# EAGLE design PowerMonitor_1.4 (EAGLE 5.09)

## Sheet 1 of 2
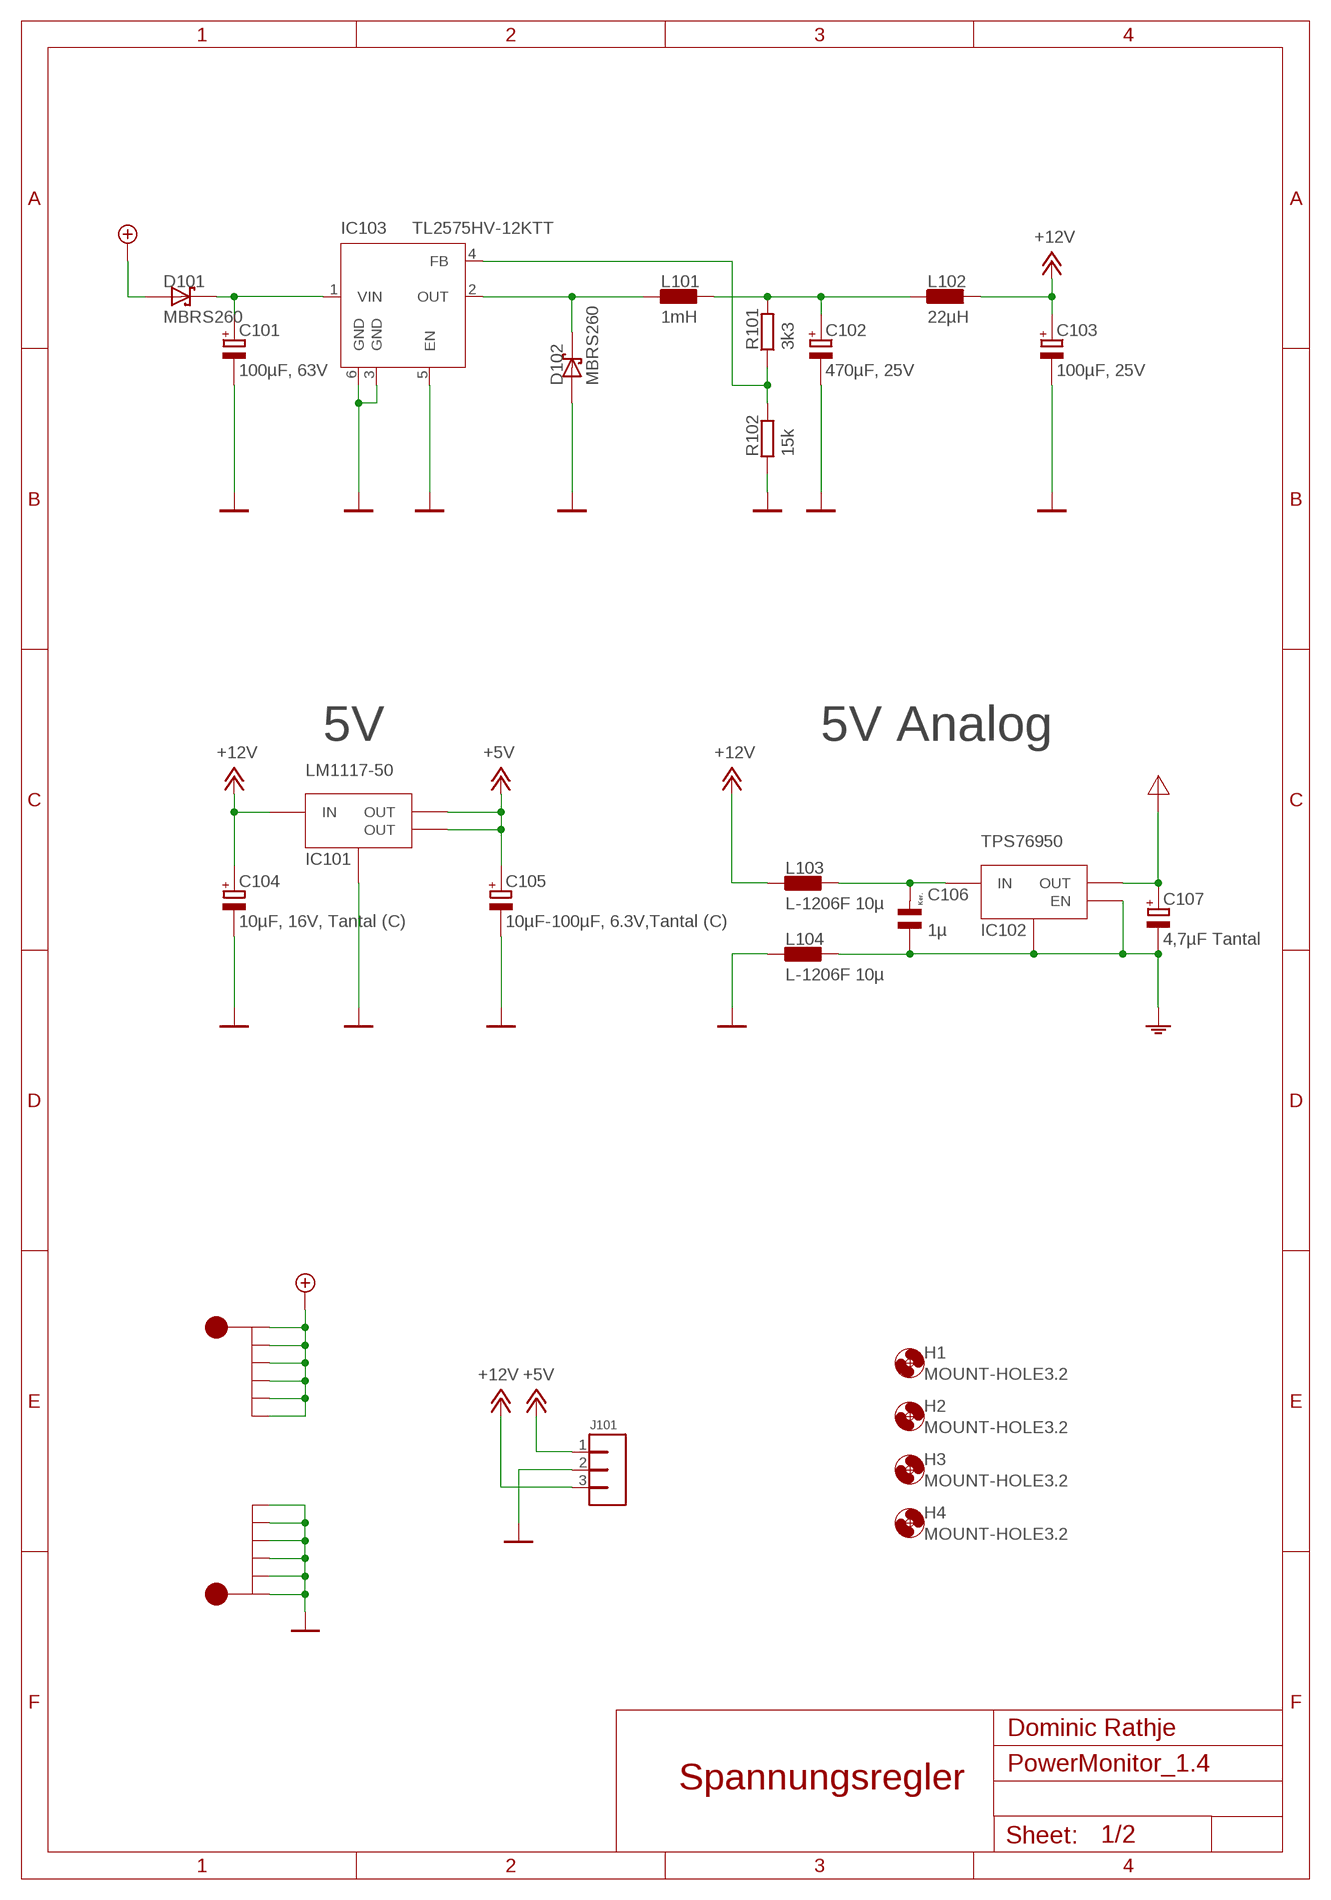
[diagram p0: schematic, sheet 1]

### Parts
C101  100µF, 63V  ELKO_SMD_10  [153CLV-1012]
C102  470µF, 25V  ELKO_SMD_10  [153CLV-1012]
C103  100µF, 25V  ELKO_SMD_08  [153CLV-0807]
C104  10µF, 16V, Tantal (C)  ELKO_SMD_C  [SMC_C]
C105  10µF-100µF, 6.3V,Tantal (C)  ELKO_SMD_C  [SMC_C]
C106  1µ  C_KER_1206  [C1206K]
C107  4,7µF Tantal  ELKO_SMD_A  [SMC_A]
D101  MBRS260  SCHOTTKY-DIODE-SMB  [SMB]
D102  MBRS260  SCHOTTKY-DIODE-SMB  [SMB]
H1  MOUNT-HOLE3.2  [3,2]
H2  MOUNT-HOLE3.2  [3,2]
H3  MOUNT-HOLE3.2  [3,2]
H4  MOUNT-HOLE3.2  [3,2]
IC101  LM1117-50  [SOT223]
IC102  TPS76950  [SOT23-5L]
IC103  TL2575HV-12KTT  [TO263-5]
J101  SL3_AKL_230  [AKL230-03]
J102  WE-SVB-6  [WE-SVB-6]
J103  WE-SVB-6  [WE-SVB-6]
L101  1mH  L_PISR  [FASTRON_PISR]
L102  22µH  L_PIS2816  [FASTRON_PIS2816]
L103  L-1206F 10µ  L_1206  [R1206]
L104  L-1206F 10µ  L_1206  [R1206]
R101  3k3  R_0805  [R0805]
R102  15k  R_0805  [R0805]

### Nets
+5V: C105.+ IC101.2(OUT) IC101.4(OUT) J101.1 ; also sheet 2
+12V: C103.+ C104.+ IC101.3(IN) J101.3 L102.2 L103.1 ; also sheet 2
AGND: C106.1 C107.- IC102.2(GND) IC102.3(EN) L104.2 ; also sheet 2
AVCC: C107.+ IC102.5(OUT) ; also sheet 2
FB: IC103.4(FB) R101.1 R102.2
GND: C101.- C102.- C103.- C104.- C105.- D102.A IC101.1(GND) IC103.3(GND) IC103.5(EN) IC103.6(GND) J101.2 J103.P$1 J103.P$2 J103.P$3 J103.P$4 J103.P$5 J103.P$6 L104.1 R102.1 ; also sheet 2
N$2: C102.+ L101.2 L102.1 R101.2
N$5: C101.+ D101.C IC103.1(VIN)
N$34: C106.2 IC102.1(IN) L103.2
SW_OUT: D102.C IC103.2(OUT) L101.1
VS: D101.A J102.P$1 J102.P$2 J102.P$3 J102.P$4 J102.P$5 J102.P$6 ; also sheet 2

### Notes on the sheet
- 5V | 5V Analog
- Dominic Rathje
- Spannungsregler

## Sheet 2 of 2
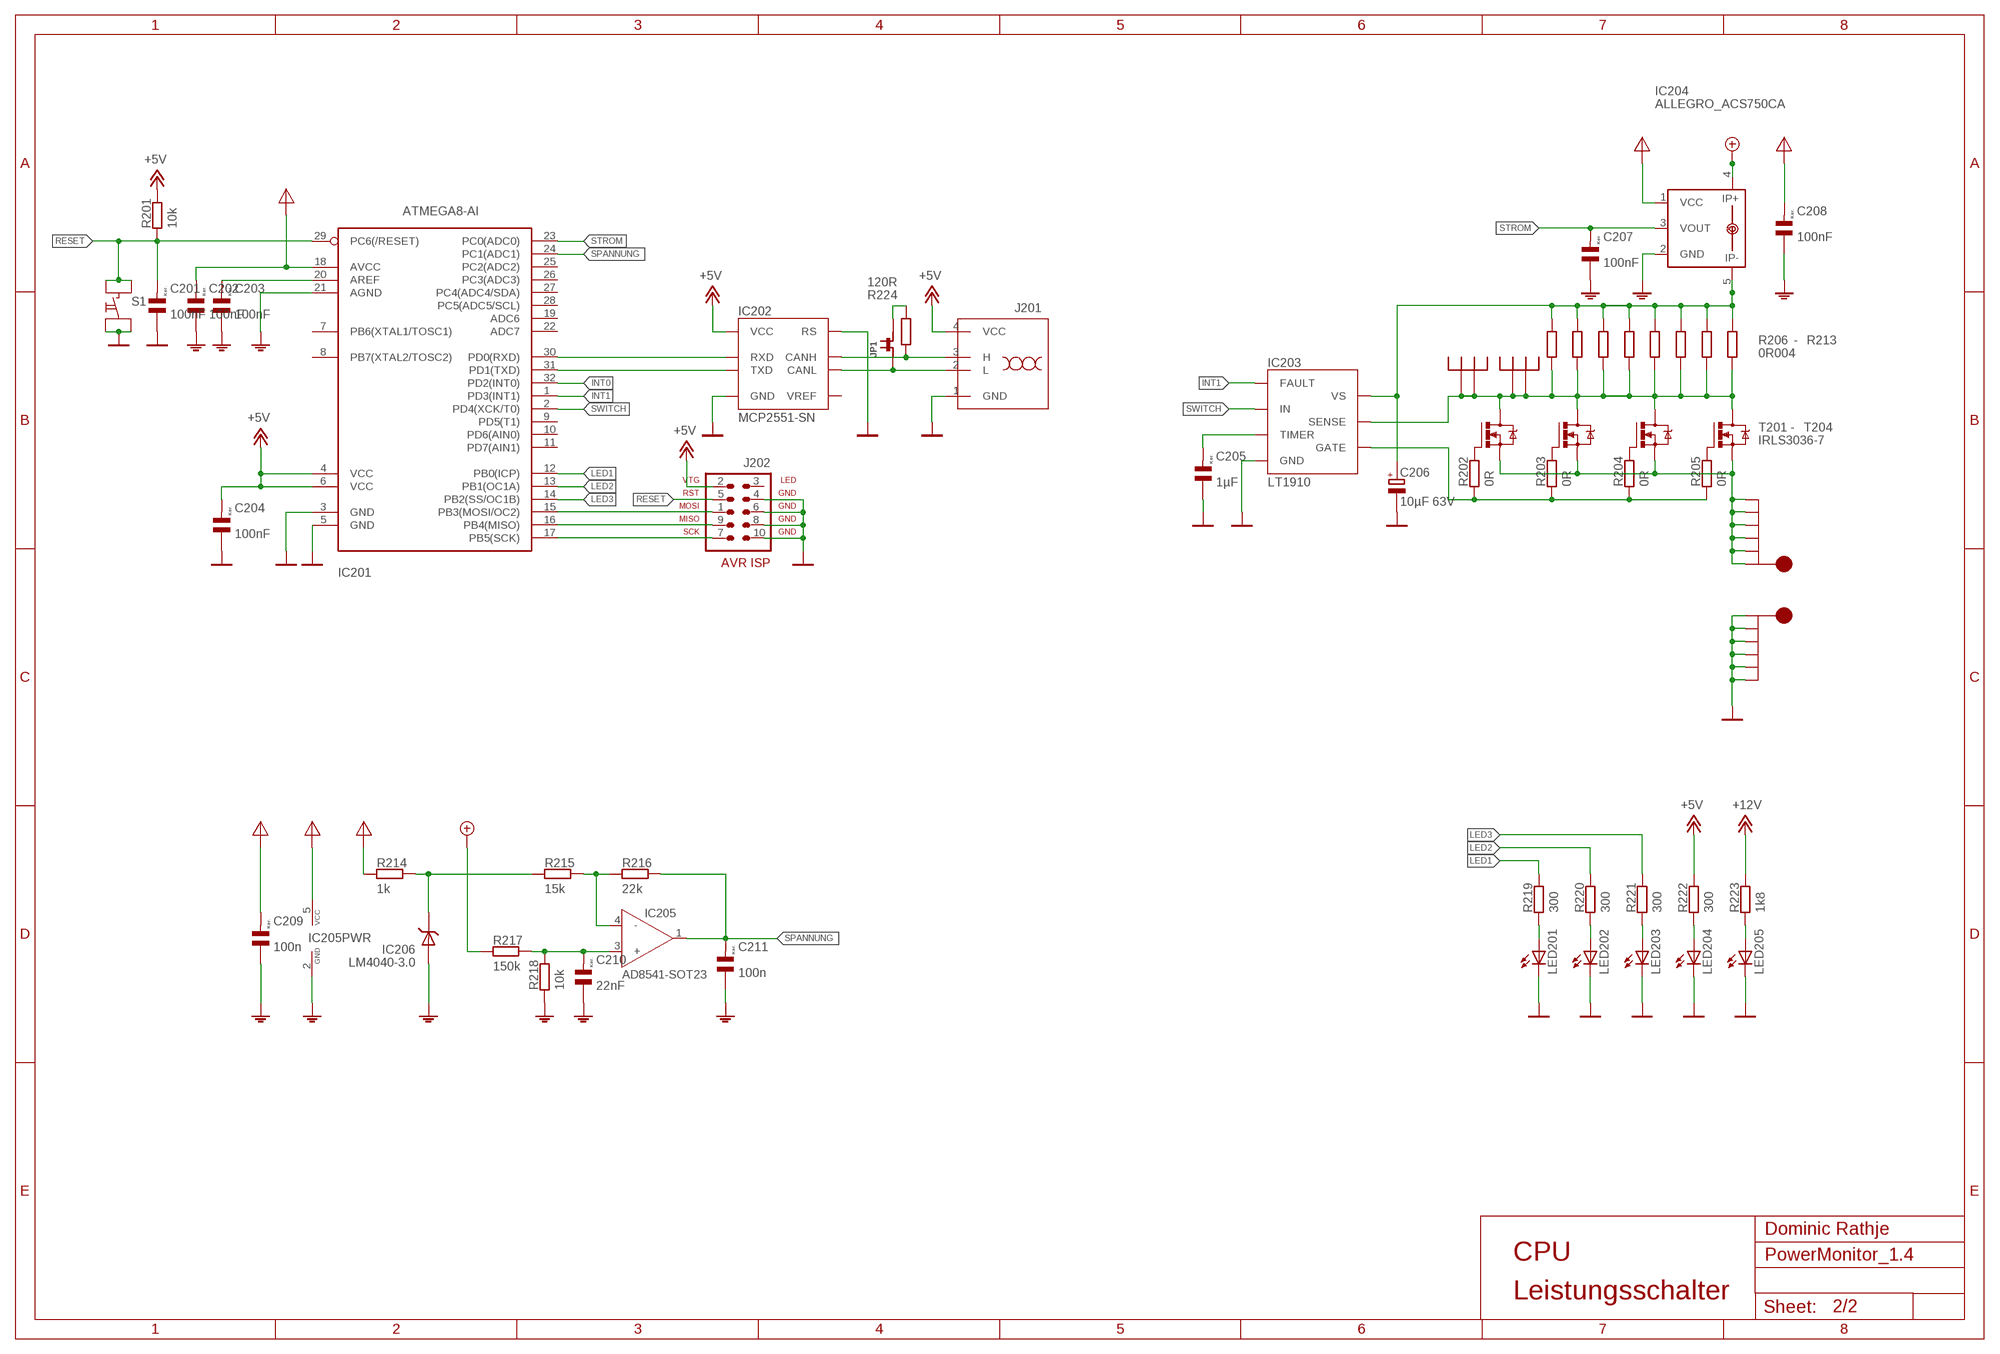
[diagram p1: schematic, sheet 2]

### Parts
C201  100nF  C_KER_0805  [C0805K]
C202  100nF  C_KER_0805  [C0805K]
C203  100nF  C_KER_0805  [C0805K]
C204  100nF  C_KER_0805  [C0805K]
C205  1µF  C_KER_1206  [C1206K]
C206  10µF 63V  ELKO_SMD_06  [153CLV-0605]
C207  100nF  C_KER_0805  [C0805K]
C208  100nF  C_KER_0805  [C0805K]
C209  100n  C_KER_0805  [C0805K]
C210  22nF  C_KER_0805  [C0805K]
C211  100n  C_KER_0805  [C0805K]
HS201  HS-D2PAK  [FISCHER_FK244_D2PAK]
HS202  HS-D2PAK  [FISCHER_FK244_D2PAK]
IC201  ATMEGA8-AI  [TQFP32-08]
IC202  MCP2551-SN  [SO08]
IC203  LT1910  [SO08]
IC204  ALLEGRO_ACS750CA  [ALLEGRO_ACS75050]
IC205  AD8541-SOT23  [SOT23-5L]
IC206  LM4040-3.0  LM4040  [SOT23]
J201  PMC_AKL182  [AKL182-04]
J202  AVR-ISP-10HG  [ML10]
J203  WE-SVB-6  [WE-SVB-6]
J204  WE-SVB-6  [WE-SVB-6]
JP1  JP1  [JP1]
LED201  LEDCHIP-LED1206  [CHIPLED_1206]
LED202  LEDCHIP-LED1206  [CHIPLED_1206]
LED203  LEDCHIP-LED1206  [CHIPLED_1206]
LED204  LEDCHIP-LED1206  [CHIPLED_1206]
LED205  LEDCHIP-LED1206  [CHIPLED_1206]
R201  10k  R_0805  [R0805]
R202  0R  R_0805  [R0805]
R203  0R  R_0805  [R0805]
R204  0R  R_0805  [R0805]
R205  0R  R_0805  [R0805]
R206  0R004  R_2010  [R2010]
R207  0R004  R_2010  [R2010]
R208  0R004  R_2010  [R2010]
R209  0R004  R_2010  [R2010]
R210  0R004  R_2010  [R2010]
R211  0R004  R_2010  [R2010]
R212  0R004  R_2010  [R2010]
R213  0R004  R_2010  [R2010]
R214  1k  R_0805  [R0805]
R215  15k  R_0805  [R0805]
R216  22k  R_0805  [R0805]
R217  150k  R_0805  [R0805]
R218  10k  R_0805  [R0805]
R219  300  R_0805  [R0805]
R220  300  R_0805  [R0805]
R221  300  R_0805  [R0805]
R222  300  R_0805  [R0805]
R223  1k8  R_0805  [R0805]
R224  120R  R_0805  [R0805]
S1  PHAP3301  [PHAP3301]
T201  IRLS3036-7  [D2PACK-7P]
T202  IRLS3036-7  [D2PACK-7P]
T203  IRLS3036-7  [D2PACK-7P]
T204  IRLS3036-7  [D2PACK-7P]

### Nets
+5V: C204.2 IC201.4(VCC) IC201.6(VCC) IC202.3(VCC) J201.4(VCC) J202.2 R201.2 R222.2 ; also sheet 1
+12V: R223.2 ; also sheet 1
AGND: C202.1 C203.1 C207.1 C208.1 C209.1 C210.1 C211.1 IC201.21(AGND) IC204.2(GND) IC205.2(GND) IC206.2(-) R218.1 ; also sheet 1
AREF: C203.2 IC201.20(AREF)
AVCC: C202.2 C208.2 C209.2 IC201.18(AVCC) IC204.1(VCC) IC205.5(VCC) R214.1 ; also sheet 1
CANH: IC202.7(CANH) J201.3(H) R224.2
CANL: IC202.6(CANL) J201.2(L) JP1.1
D: HS201.P$1 HS201.P$2 HS202.P$1 HS202.P$2 IC203.6(SENSE) R206.P$1 R207.P$1 R208.P$1 R209.P$1 R210.P$1 R211.P$1 R212.P$1 R213.P$1 T201.D T202.D T203.D T204.D
G: IC203.5(GATE) R202.1 R203.1 R204.1 R205.1
GND: C201.1 C204.1 C205.1 C206.- IC201.3(GND) IC201.5(GND) IC202.2(GND) IC202.8(RS) IC203.1(GND) J201.1(GND) J202.4 J202.6 J202.8 J202.10 J204.P$1 J204.P$2 J204.P$3 J204.P$4 J204.P$5 J204.P$6 LED201.C LED202.C LED203.C LED204.C LED205.C S1.3 S1.4 ; also sheet 1
INT0: IC201.32(PD2(INT0))
INT1: IC201.1(PD3(INT1)) IC203.3(FAULT)
LED1: IC201.12(PB0(ICP)) R219.2
LED2: IC201.13(PB1(OC1A)) R220.2
LED3: IC201.14(PB2(SS/OC1B)) R221.2
MISO: IC201.16(PB4(MISO)) J202.9
MOSI: IC201.15(PB3(MOSI/OC2)) J202.1
N$1: C205.2 IC203.2(TIMER)
N$3: LED201.A R219.1
N$4: LED202.A R220.1
N$6: LED203.A R221.1
N$7: IC206.1(+) R214.2 R215.1
N$8: IC205.4(-) R215.2 R216.1
N$9: C210.2 IC205.3(+) R217.2 R218.2
N$10: R202.2 T201.G
N$11: R203.2 T202.G
N$12: R204.2 T203.G
N$13: R205.2 T204.G
N$14: LED204.A R222.1
N$15: LED205.A R223.1
N$16: JP1.2 R224.1
RESET: C201.2 IC201.29(PC6(/RESET)) J202.5 R201.1 S1.1 S1.2
RXD: IC201.30(PD0(RXD)) IC202.4(RXD)
S: J203.P$1 J203.P$2 J203.P$3 J203.P$4 J203.P$5 J203.P$6 T201.S T202.S T203.S T204.S
SCK: IC201.17(PB5(SCK)) J202.7
SPANNUNG: C211.2 IC201.24(PC1(ADC1)) IC205.1(O) R216.2
STROM: C207.2 IC201.23(PC0(ADC0)) IC204.3(VOUT)
SWITCH: IC201.2(PD4(XCK/T0)) IC203.4(IN)
TXD: IC201.31(PD1(TXD)) IC202.1(TXD)
VS: IC204.4(IP+) IC204.IP+1 R217.1 ; also sheet 1
VS_: C206.+ IC203.8(VS) IC204.5(IP-) IC204.IP-1 R206.P$2 R207.P$2 R208.P$2 R209.P$2 R210.P$2 R211.P$2 R212.P$2 R213.P$2
Unconnected: IC201.7(PB6(XTAL1/TOSC1)) IC201.8(PB7(XTAL2/TOSC2)) IC201.9(PD5(T1)) IC201.10(PD6(AIN0)) IC201.11(PD7(AIN1)) IC201.19(ADC6) IC201.22(ADC7) IC201.25(PC2(ADC2)) IC201.26(PC3(ADC3)) IC201.27(PC4(ADC4/SDA)) IC201.28(PC5(ADC5/SCL)) IC202.5(VREF) J202.3

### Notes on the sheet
- -
- -
- Dominic Rathje
- CPU
- Leistungsschalter

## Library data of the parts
C101-C105 C107 C206 = lib-rcl:ELKO
C106 C201-C205 C207-C211 = lib-rcl:C_KER
D101 D102 = lib-halbleiter:SCHOTTKY-DIODE
H1-H4 = holes:MOUNT-HOLE: MOUNTING HOLE with drill center marker
HS201 HS202 = lib-mechanic:HS-D2PAK
IC101 = lib-ic:LM1117-*: Alternativ auch TLV1117 von TI
IC102 = lib-ic:TPS769*
IC103 = lib-ic:TL2575HV-*KTT
IC201 = lib-avr:ATMEGA8: MICROCONTROLLER 8 Kbytes FLASH 1 kbytes SRAM 512 bytes EEPROM USART 6-channel 10 bit ADC 2-channel 8 bit ADC
IC202 = lib-ic:MCP2551-?: High-Speed CAN Transceiver
IC203 = lib-ic:LT1910: Protected High Side MOSFET Driver
IC204 = lib-ic:ALLEGRO_ACS750*CA: Current Sensor display layer 49 Reference in BRD and place VIAs on circles Source: www.allegromicro.com/datafile/0750-050.pdf
IC205 = lib-ic:AD8541
IC206 = lib-ic:LM4040
J101 = lib-connectors:SL3?
J102 J103 J203 J204 = lib-connectors:WE-SVB-6
J201 = lib-com:PMC: Poor-Mans-CAN
J202 = lib-avr:AVR-ISP-10: AVR ISP-10 Serial Programming Header
JP1 = lib-connectors:JP1
L101-L104 = lib-rcl:L
LED201-LED205 = lib-halbleiter:LED
R101 R102 R201-R224 = lib-rcl:R: RESISTOR, European symbol
S1 = lib-switch:PHAP?*
T201-T204 = lib-halbleiter:IRLS3036-7

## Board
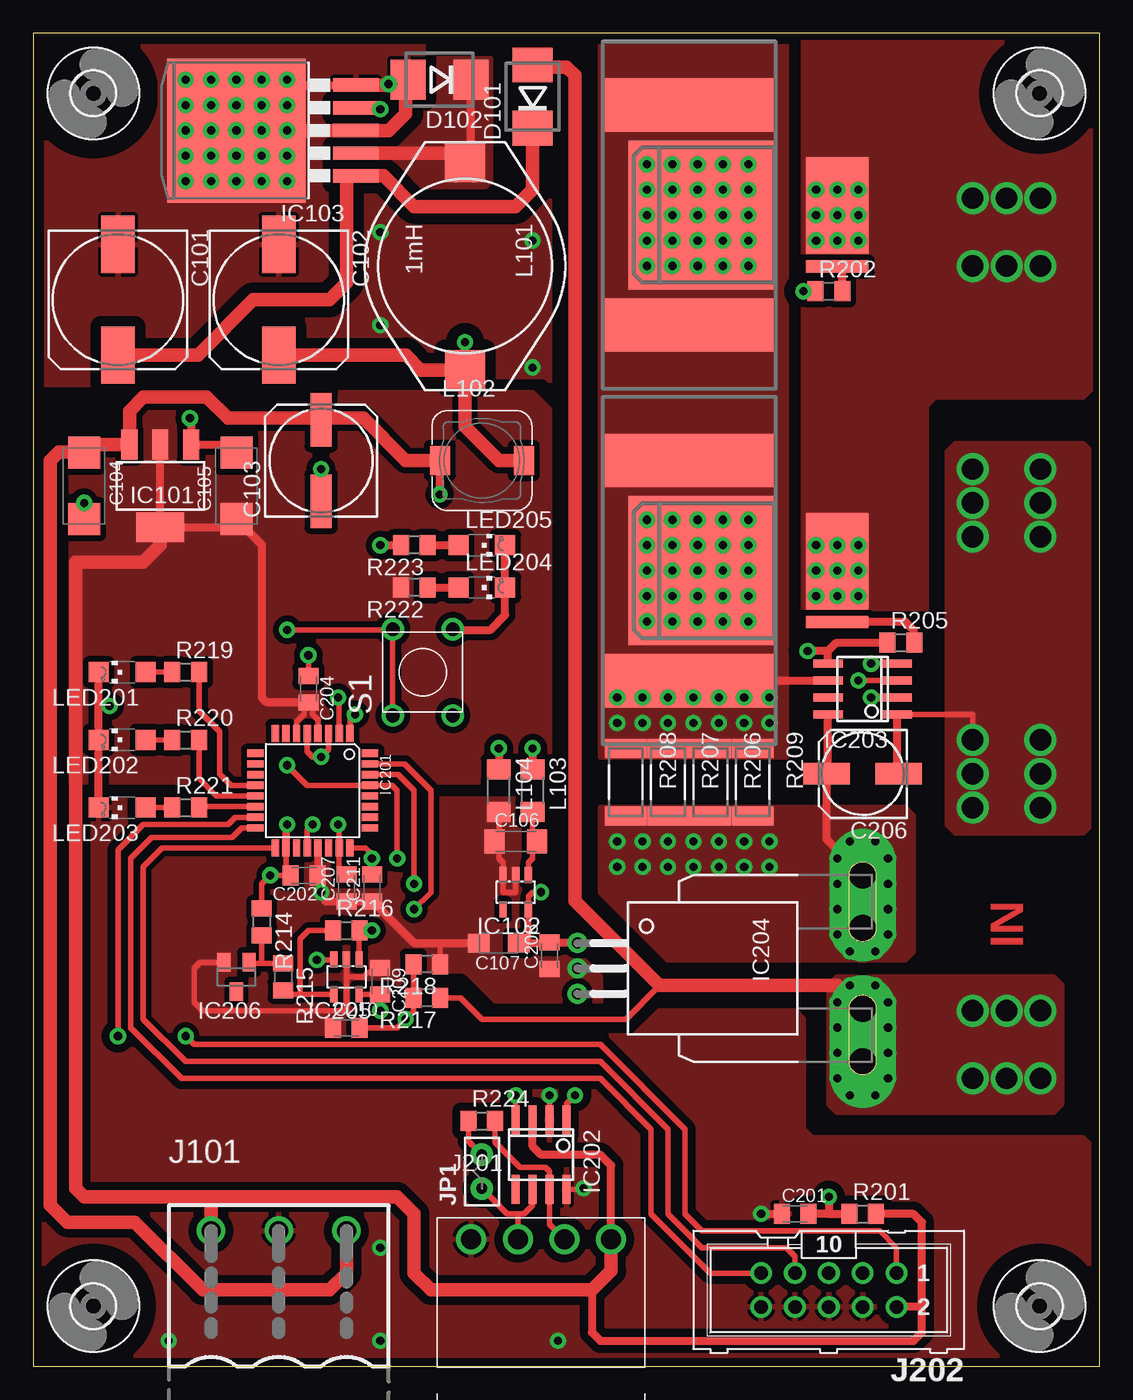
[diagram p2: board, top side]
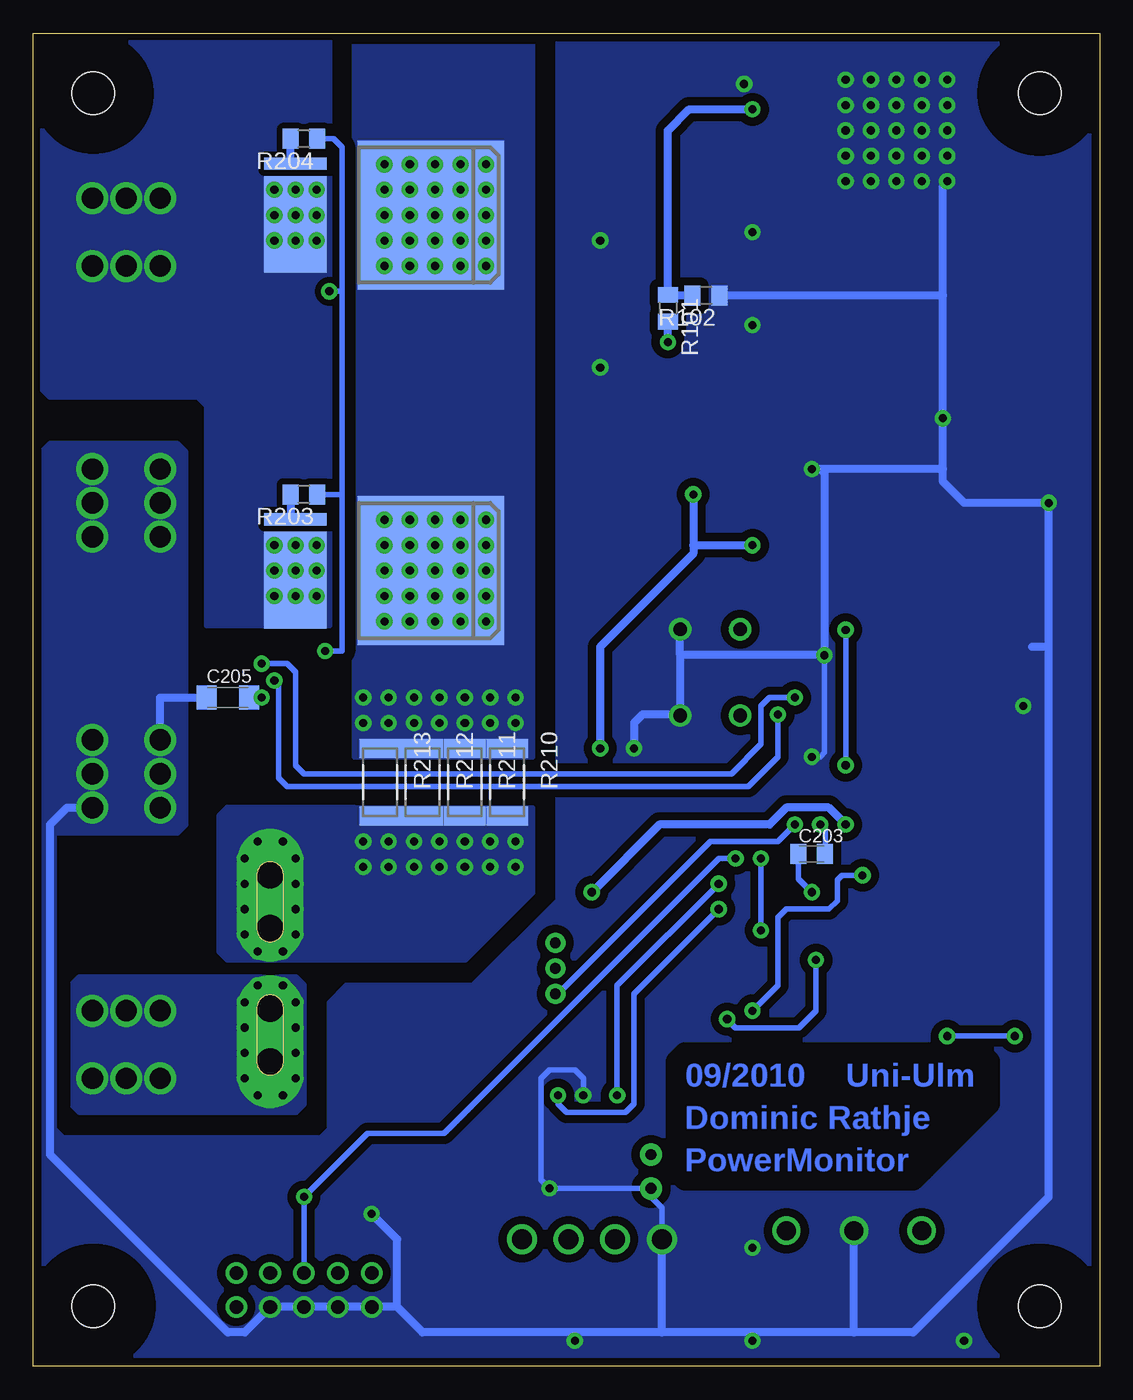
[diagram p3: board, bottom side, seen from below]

Size 80 x 100 mm. Coordinates in mm from the lower left corner, seen from the top.
Outline: 0,0 80,0 80,100 0,100 0,0
Copper layers (1*16): Top 0.0254mm / dielectric 1.4986mm / Bottom 0.0254mm
Design rules "uni_ulm_power": minimum track width 16mil, minimum drill 24mil, track to track 12mil, track to pad 12mil, pad to pad 12mil, via to via 12mil, smd to smd 8mil, copper to edge 20mil, drill to drill 8mil, minimum pad ring 12mil, minimum via ring 12mil, stop-mask expansion 4mil, vias tented up to drill 24mil, thermal gap 10mil
tRestrict: 3 lines
bRestrict: area 8.3,14 to 31.8,23.5

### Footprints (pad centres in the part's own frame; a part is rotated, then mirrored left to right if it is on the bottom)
153CLV-1012 = smd 4.3 x 2.5: + 4.15,0; - -4.15,0
153CLV-0807 = smd 4 x 1.6: + 3.05,0; - -3.05,0
SMC_C = smd 2.4 x 2.4: + -2.5,0; - 2.5,0
C1206K = smd 1.5 x 1.8: 1 -1.6,0; 2 1.6,0
SMC_A = smd 1.6 x 1.4: + -1.5,0; - 1.5,0
C0805K = smd 1.2 x 1.5: 1 -1,0; 2 1,0
153CLV-0605 = smd 3.5 x 1.6: + 2.7,0; - -2.7,0
SMB = smd 2.6 x 3: A 2.368,0; C -2.368,0
3,2 = hole 3.2: 0,0
FISCHER_FK244_D2PAK = smd 4 x 13.107: P$1 8.255,0; P$2 -8.255,0
SOT223 = smd 1.219 x 2.235: 1 -2.311,-3.099; 2 0,-3.099; 3 2.311,-3.099 | smd 3.6 x 2.2: 4 0,3.099
SOT23-5L = smd 0.55 x 1.2: 1 -0.95,-1.3; 2 0,-1.3; 3 0.95,-1.3; 4 0.95,1.3; 5 -0.95,1.3
TO263-5 = smd 1 x 3.4: 1 -3.404,-6.426; 2 -1.702,-6.426; 3 0,-6.426; 4 1.702,-6.426; 5 3.404,-6.426 | smd 10.8 x 10.41: 6 0,2.54
TQFP32-08 = smd 1.27 x 0.559: 1 -4.293,2.8; 2 -4.293,2; 3 -4.293,1.2; 4 -4.293,0.4; 5 -4.293,-0.4; 6 -4.293,-1.2; 7 -4.293,-2; 8 -4.293,-2.8; 17 4.293,-2.8; 18 4.293,-2; 19 4.293,-1.2; 20 4.293,-0.4; 21 4.293,0.4; 22 4.293,1.2; 23 4.293,2; 24 4.293,2.8 | smd 0.559 x 1.27: 9 -2.8,-4.293; 10 -2,-4.293; 11 -1.2,-4.293; 12 -0.4,-4.293; 13 0.4,-4.293; 14 1.2,-4.293; 15 2,-4.293; 16 2.8,-4.293; 25 2.8,4.293; 26 2,4.293; 27 1.2,4.293; 28 0.4,4.293; 29 -0.4,4.293; 30 -1.2,4.293; 31 -2,4.293; 32 -2.8,4.293
SO08 = smd 0.6 x 2.2: 1 -1.905,-2.6; 2 -0.635,-2.6; 3 0.635,-2.6; 4 1.905,-2.6; 5 1.905,2.6; 6 0.635,2.6; 7 -0.635,2.6; 8 -1.905,2.6
ALLEGRO_ACS75050 = drill 0.8 pad 1.5 round: 1 -1.91,-21.4; 2 0,-21.4; 3 1.91,-21.4 | drill 2 pad 5 offset: 4 3,0; 5 -3,0 | drill 2 pad 4 offset: IP+1 7,0; IP-1 -7,0
SOT23 = smd 1 x 1.4: 1 -0.95,-1.1; 2 0.95,-1.1; 3 0,1.1
AKL230-03 = drill 1.422 pad 2.032 round: 1 -5.08,0; 2 0,0; 3 5.08,0
WE-SVB-6 = drill 1.6 pad 2.235 round: P$1 0,-2.54; P$2 2.54,-2.54; P$3 -2.54,-2.54; P$4 -2.54,2.54; P$5 0,2.54; P$6 2.54,2.54
AKL182-04 = drill 1.5 pad 2.184 round: 1 -5.25,0; 2 -1.75,0; 3 1.75,0; 4 5.25,0
ML10 = drill 1.016 pad 1.626 round: 1 -5.08,-1.27; 2 -5.08,1.27; 3 -2.54,-1.27; 4 -2.54,1.27; 5 0,-1.27; 6 0,1.27; 7 2.54,-1.27; 8 2.54,1.27; 9 5.08,-1.27; 10 5.08,1.27
JP1 = drill 0.813 pad 1.676 round: 1 -1.27,0; 2 1.27,0
FASTRON_PISR = smd 3 x 3: 1 -7.8,0; 2 7.8,0
FASTRON_PIS2816 = smd 1.5 x 2.2: 1 3.15,0; 2 -3.15,0
R1206 = smd 1.5 x 1.8: 1 -1.6,0; 2 1.6,0
CHIPLED_1206 = smd 1.5 x 1.5: A 0,-1.75; C 0,1.75
R0805 = smd 1.2 x 1.5: 1 -1,0; 2 1,0
R2010 = smd 1.44 x 3.12: P$1 -2.54,0; P$2 2.54,0
PHAP3301 = drill 1.016 pad 1.676 round: 1 -2.235,-3.251; 2 -2.235,3.226; 3 2.261,-3.251; 4 2.261,3.226
D2PACK-7P = smd 11.176 x 11: D 0,1.27 | smd 0.914 x 4.699: G -3.85,-8.89 | smd 7.264 x 4.699: S 0.7,-8.89

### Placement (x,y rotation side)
C101  6.35,80.01 270 top
C102  18.41,80.01 270 top
C103  21.59,67.94 90 top
C104  3.81,66.04 270 top
C105  15.24,66.04 90 top
C106  36.2,39.37 0 top
C107  34.92,31.75 180 top
C201  57.15,11.43 0 top
C202  20.32,36.83 180 top
C203  21.59,38.42 0 bottom
C204  20.64,50.8 270 top
C205  65.41,50.16 0 bottom
C206  62.23,44.45 180 top
C207  23.5,35.88 90 top
C208  38.73,30.8 90 top
C209  26.04,28.89 270 top
C210  23.5,25.4 0 top
C211  25.4,35.88 90 top
D101  37.47,95.25 90 top
D102  30.48,96.52 180 top
H1  4.5,4.5 0 top
H2  75.5,4.5 0 top
H3  75.5,95.5 0 top
H4  4.5,95.5 0 top
HS201  49.21,86.36 90 top
HS202  49.21,59.69 90 top
IC101  9.53,66.04 180 top
IC102  36.2,35.56 180 top
IC103  17.78,92.71 90 top
IC201  20.95,43.18 270 top
IC202  38.1,15.88 180 top
IC203  62.23,50.8 90 top
IC204  62.23,29.84 270 top
IC205  23.5,29.21 180 top
IC206  15.24,29.21 180 top
J101  18.41,10.16 0 top
J102  73.03,24.13 0 top
J103  73.03,64.77 270 top
J201  38.1,9.53 0 top
J202  59.69,5.71 180 top
J203  73.03,85.09 0 top
J204  73.03,44.45 90 top
JP1  33.66,14.61 90 top
L101  32.38,82.55 270 top
L102  33.66,67.94 0 top
L103  37.47,43.18 270 top
L104  34.92,43.18 270 top
LED201  6.67,52.07 90 top
LED202  6.67,46.99 90 top
LED203  6.67,41.91 90 top
LED204  33.66,58.42 270 top
LED205  33.66,61.59 270 top
R101  32.38,79.38 270 bottom
R102  29.53,80.33 180 bottom
R201  62.23,11.43 0 top
R202  59.69,80.64 0 top
R203  59.69,65.41 180 bottom
R204  59.69,92.08 180 bottom
R205  65.09,54.29 0 top
R206  50.8,43.81 270 top
R207  47.62,43.81 270 top
R208  44.45,43.81 270 top
R209  53.98,43.81 270 top
R210  44.45,43.81 270 bottom
R211  47.62,43.81 270 bottom
R212  50.8,43.81 270 bottom
R213  53.98,43.81 270 bottom
R214  17.14,33.34 270 top
R215  18.73,29.21 270 top
R216  23.5,32.7 0 top
R217  29.53,27.62 180 top
R218  29.53,30.16 180 top
R219  11.43,52.07 0 top
R220  11.43,46.99 0 top
R221  11.43,41.91 0 top
R222  28.57,58.42 180 top
R223  28.57,61.59 180 top
R224  33.66,18.41 0 top
S1  29.21,52.07 0 top
T201  51.44,86.36 90 top
T202  51.44,59.69 270 bottom
T203  51.44,86.36 270 bottom
T204  51.44,59.69 90 top

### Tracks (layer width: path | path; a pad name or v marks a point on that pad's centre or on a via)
+5V
  Top 0.406: IC201.6 19.75,48.33 20.32,48.9 20.32,49.48 C204.2 | IC201.4 21.36,48.49 20.95,48.9 20.95,49.48 C204.2 | 20.59,49.85 C204.2
  Top 0.61: IC101.2 IC101.4 14.64,62.94 C105.+ 17.14,61.63 17.14,50.16 17.46,49.85 20.59,49.85 | R201.2 66.04,11.43 66.67,10.79 66.67,4.45 | IC202.3 37.47,16.51 38.1,15.88 42.55,15.88 43.35,15.07 J201.4 | 66.67,4.45 66.67,2.54 66.04,1.91 42.55,1.91 41.91,2.54 41.91,5.71 | 66.67,4.45 J202.2
  Top 1.016: IC101.4 9.53,61.59 8.26,60.33 3.17,60.33 3.17,13.34 3.81,12.7 13.34,12.7 | J201.4 43.35,7.16 41.91,5.71 29.84,5.71 28.57,6.99 28.57,11.43 27.3,12.7 13.34,12.7 | 13.34,12.7 J101.1
  pour Top (isolate 0.457, no thermals): 2.86,73.03 37.47,73.03 38.73,71.75 38.73,45.09 37.47,43.81 2.86,43.81
+12V  (via drill 0.61 pad 0.81)
  Top 0.61: 3.89,69.14 3.81,69.22 C104.+ | v37.47,46.35 L103.1 | v30.48,65.41 30.48,67.92 L102.2 | v26.04,61.59 R223.2
  Top 1.016: 3.89,69.14 IC101.3 7.21,71.67 8.26,72.71 13.02,72.71 14.61,71.12 21.46,71.12 C103.+ 21.71,71.12 24.77,71.12 27.94,67.94 L102.2 | J101.3 23.5,6.99 22.23,5.71 12.7,5.71 7.62,10.79 2.54,10.79 1.27,12.06 1.27,67.94 1.91,68.58 3.77,68.58 C104.+
  Bottom 0.61: v37.47,46.35 37.47,53.98 30.48,60.96 30.48,61.59 | v30.48,65.41 30.48,61.59 | 30.48,61.59 v26.04,61.59
AGND  (via drill 0.61 pad 0.81)
  Top 0.406: IC102.2 36.2,35.56 35.24,35.56 IC102.3 35.24,37.78 34.92,38.1 34.92,39.04 C106.1 34.92,39.7 L104.2 | 23.5,29.21 IC205.2 | 23.5,29.21 24.77,29.21 25.08,29.53 25.67,29.53 C209.1 | R218.1 30.53,31.7 30.48,31.75 | IC206.2 12.53,30.31 12.06,29.84 12.06,27.3 12.7,26.67 23.5,26.67 23.5,29.21 | v21.59,35.56 21.59,36.56 C202.1
  Top 0.559: 21.36,37.11 IC201.21
  Top 0.61: 21.91,34.88 C207.1 C211.1 25.45,34.88 28.57,31.75 30.48,31.75 C107.-
  Bottom 0.406: C203.1 22.59,36.56 v21.59,35.56
  pour Top (isolate 0.406, no thermals): 42.55,24.77 7.62,24.77 7.62,42.55 38.73,42.55 38.73,33.02 42.55,29.21
AREF  (via drill 0.61 pad 0.81)
  Top 0.406: IC201.20 20.55,40.24 v20.95,40.64
  Bottom 0.406: v20.95,40.64 20.55,40.24 IC201.20 20.55,38.45 C203.2
AVCC  (via drill 0.61 pad 0.81)
  Top 0.406: v38.1,35.56 37.47,35.56 37.15,35.24 IC102.5 37.15,31.84 C107.+ | IC205.5 26.02,27.91 C209.2 v26.04,26.67 | 19.05,36.83 v17.78,36.83 17.14,36.2 R214.1 | 19.05,36.83 C202.2 | IC201.18 18.95,36.92 19.05,36.83
  Top 0.559: IC201.18 18.95,40.55 v19.05,40.64
  Top 0.61: C107.+ 38.69,31.75 C208.2 40.79,31.8 IC204.1
  Bottom 0.406: v26.04,26.67 24.13,28.57 24.13,33.66 23.5,34.29 20.32,34.29 19.68,34.92 19.68,36.47 C202.2 v17.78,36.83
  Bottom 0.61: v38.1,35.56 33.02,40.64 24.77,40.64 23.5,41.91 20.32,41.91 v19.05,40.64
CANH
  Top 0.406: J201.3 38.73,10.64 IC202.7 38.73,14.61 38.42,14.92 36.51,14.92 34.66,16.78 R224.2
CANL
  Top 0.406: JP1.1 35.56,11.43 36.2,11.43 | 36.2,11.43 36.83,11.43 37.47,12.06 IC202.6 | J201.2 36.35,11.28 36.2,11.43
D  (via drill 0.61 pad 0.81)
  Top 0.61: IC203.6 55.24,51.44 v55.24,50.16
  other vias: 46.04,55.88 46.04,57.78 46.04,59.69 46.04,61.59 46.04,63.5 47.94,55.88 47.94,57.78 47.94,59.69 47.94,61.59 47.94,63.5 49.85,63.5 49.85,61.59 49.85,59.69 49.85,57.78 49.85,55.88 51.75,55.88 51.75,57.78 51.75,59.69 51.75,61.59 51.75,63.5 53.66,63.5 53.66,61.59 53.66,59.69 53.66,57.78 53.66,55.88 46.04,82.55 46.04,84.45 46.04,86.36 46.04,88.27 46.04,90.17 47.94,90.17 47.94,88.27 47.94,86.36 47.94,84.45 47.94,82.55 49.85,82.55 51.75,82.55 53.66,82.55 53.66,84.45 51.75,84.45 49.85,84.45 49.85,88.27 49.85,90.17 51.75,90.17 53.66,90.17 53.66,88.27 51.75,88.27 51.75,86.36 53.66,86.36 49.85,86.36 43.81,48.26 45.72,48.26 47.62,48.26 49.53,48.26 51.44,48.26 53.34,48.26 55.24,48.26 43.81,50.16 45.72,50.16 47.62,50.16 49.53,50.16 51.44,50.16 53.34,50.16
  pour Top (isolate 0.813, rank 2, no thermals): 56.52,45.72 42.55,45.72 42.55,99.69 56.52,99.69
  pour Bottom (isolate 0.813, rank 2, no thermals): 55.88,45.72 42.55,45.72 42.55,99.69 55.88,99.69
FB  (via drill 0.61 pad 0.81)
  Top 0.61: IC103.4 25.92,94.41 v26.04,94.3
  Bottom 0.61: v26.04,94.3 30.8,94.3 32.38,92.71 R101.1 30.57,80.38 arc90 R102.2
G  (via drill 0.61 pad 0.81)
  Top 0.61: 59.63,53.66 v58.1,53.66 | IC203.5 59.63,53.66 | v57.78,80.64 R202.1 | 59.63,53.66 60.27,54.29 R205.1
  Bottom 0.406: v58.1,53.66 56.83,53.66 56.83,65.41 | 56.83,80.64 v57.78,80.64 | 56.83,65.41 56.83,80.64 | 56.83,65.41 R203.1 | R204.1 57.47,92.08 56.83,91.44 56.83,80.64
GND  (via drill 0.61 pad 0.81)
  Top 0.406: v20.64,53.34 C204.1 | v38.73,20.32 IC202.2 | IC202.8 41.22,13.28 v41.27,13.34 | IC203.1 70.48,48.9 J204.P$6 | IC201.5 20.55,46.12 20.95,45.72 v21.59,45.72 22.16,46.28 IC201.3
  Top 0.61: IC103.5 18.64,96.11 IC103.6 | v11.75,71.12 11.84,71.03 IC101.1 15.16,69.14 15.24,69.22 C105.- | v3.81,64.77 C104.- | v21.59,67.31 C103.- | IC203.1 64.83,44.55 C206.- | v34.92,46.35 L104.1 | v54.61,11.43 C201.1 | LED203.C LED202.C LED201.C 5.08,52.07 | v5.71,49.53 5.08,49.53 | LED205.C LED204.C 35.41,56.36 34.29,55.24 31.52,55.24 S1.4
  Top 1.016: 26.67,96.11 28.11,96.11 D102.A 27.94,96.35 27.94,93.98 26.67,92.71 IC103.3 v19.05,92.71 | IC103.5 26.67,96.11 | 26.67,96.11 v26.67,96.2 | v11.43,88.9 11.09,88.56
  Bottom 0.406: v20.64,53.34 20.64,46.04 20.95,45.72 | S1.3 31.55,48.9 | v38.73,20.32 38.73,21.59 39.37,22.23 41.27,22.23 41.91,21.59 41.91,13.97 v41.27,13.34 34.29,13.34 32.85,11.89 J201.1
  Bottom 0.61: 11.75,67.31 11.75,66.36 10.16,64.77 v3.81,64.77 3.81,53.98 | 11.75,67.31 v11.75,71.12 11.75,80.33 | 11.75,67.31 20.95,67.31 | 20.95,67.31 v21.59,67.31 | 52.7,4.45 J202.10 J202.8 J202.6 J202.4 64.14,2.54 65.41,2.54 78.74,15.88 78.74,40.64 77.47,41.91 J204.P$3 | 52.7,4.45 50.8,2.54 32.85,2.54 | 18.41,2.54 13.97,2.54 3.81,12.7 3.81,53.98 | 11.75,80.33 11.75,88.58 v11.43,88.9 | 18.41,2.54 J101.2 | 32.85,2.54 J201.1 | 18.41,2.54 32.85,2.54 | 20.95,67.31 20.64,66.99 v20.64,53.34 31.47,53.34 | 11.75,80.33 R102.1 | v54.61,11.43 52.7,9.53 52.7,4.45 | 31.47,53.34 S1.3 | 31.47,53.34 S1.4 | 31.55,48.9 34.29,48.9 34.92,48.26 v34.92,46.35 | C205.1 70.48,50.16 J204.P$6 | 3.81,53.98 5.08,53.98
  other vias: 19.05,88.9 17.14,88.9 15.24,88.9 13.34,88.9 11.43,90.81 11.43,92.71 11.43,94.61 11.43,96.52 13.34,96.52 13.34,94.61 13.34,92.71 13.34,90.81 15.24,90.81 15.24,92.71 15.24,94.61 15.24,96.52 17.14,96.52 17.14,94.61 17.14,92.71 17.14,90.81 19.05,90.81 19.05,94.61 19.05,96.52 37.47,74.93 37.47,84.45 26.04,85.09 26.04,78.11 39.37,1.91 10.16,1.91 26.04,8.89 26.04,1.91
  pour Top (isolate 0.61, no thermals): 69.22,69.22 68.58,68.58 68.58,40.64 69.22,40.01 78.74,40.01 79.38,40.64 79.38,68.58 78.74,69.22
  pour Bottom (isolate 0.61, no thermals): 69.22,69.22 68.58,68.58 68.58,40.64 69.22,40.01 78.74,40.01 79.38,40.64 79.38,68.58 78.74,69.22
  pour Bottom (isolate 0.61, no thermals): -0.64,100.33 -0.64,-0.64 80.64,-0.64 80.64,40.64 78.42,40.64 78.42,17.78 77.79,17.14 58.42,17.14 57.78,17.78 57.78,27.3 56.52,28.57 46.99,28.57 40.64,34.92 40.64,100.33
  pour Top (isolate 0.813, rank 2): -0.64,100.33 -0.64,73.66 38.73,73.66 38.73,100.33
  pour Top (no thermals): 9.53,98.42 9.53,87 20.95,87 20.95,98.42
  pour Top (isolate 0.61, rank 4): 80.01,0 0,0 0,42.55 40.64,42.55 40.64,24.77 45.09,24.77 46.99,26.67 57.15,26.67 57.78,26.04 57.78,17.78 58.42,17.14 78.74,17.14 80.01,15.88
INT1  (via drill 0.61 pad 0.81)
  Top 0.406: v61.91,51.44 IC203.3 | 23.81,48.58 v24.13,48.9 23.75,48.52 IC201.1
  Bottom 0.406: v24.13,48.9 24.13,45.72 26.35,43.5 60.96,43.5 61.59,44.13 61.59,51.12 v61.91,51.44
LED1
  Top 0.406: IC201.12 14.84,43.58 13.97,44.45 13.97,47.62 12.43,49.16 R219.2
LED2
  Top 0.406: IC201.13 13.73,42.78 12.43,44.09 R220.2
LED3
  Top 0.406: IC201.14 12.5,41.98 R221.2
MISO
  Top 0.406: J202.9 50.8,6.99 46.35,11.43 46.35,17.78 42.55,21.59 11.11,21.59 7.3,25.4 7.3,38.1 8.89,39.69 14.92,39.69 15.62,40.38 IC201.16
MOSI  (via drill 0.61 pad 0.81)
  Top 0.406: J202.1 64.77,8.89 63.5,10.16 50.16,10.16 48.9,11.43 48.9,17.78 42.55,24.13 12.06,24.13 v11.43,24.77 | IC201.15 15.14,41.18 14.61,40.64 8.26,40.64 6.35,38.73 v6.35,24.77
  Bottom 0.406: v6.35,24.77 v11.43,24.77
N$1  (via drill 0.61 pad 0.81)
  Top 0.61: v62.87,50.16 IC203.2
  Bottom 0.61: v62.87,50.16 C205.2
N$2  (via drill 0.61 pad 0.81)
  Top 0.61: L101.2 v32.38,76.83
  Top 1.016: C102.+ 27.96,75.86 29.07,74.75 L101.2 32.38,70.48 34.92,67.94 L102.1
  Bottom 0.61: v32.38,76.83 R101.2
N$3
  Top 0.406: LED201.A R219.1
N$4
  Top 0.406: LED202.A R220.1
N$5
  Top 1.016: D101.C 37.47,88.27 36.2,87 28.57,87 26.26,89.31 IC103.1 23.5,89.31 23.5,81.28 22.23,80.01 16.51,80.01 12.36,75.86 C101.+
N$6
  Top 0.406: LED203.A R221.1
N$7
  Top 0.406: 17.14,30.21 16.29,30.21 IC206.1 | 17.14,30.21 R214.2 | 17.14,30.21 R215.1
N$8
  Top 0.406: R216.1 20.64,32.7 20,32.07 20,27.91 | 20,27.91 19.03,27.91 R215.2 | IC205.4 20.32,27.91 20,27.91
N$9  (via drill 0.61 pad 0.81)
  Top 0.406: R218.2 R217.2 28.53,26.62 v27.94,26.04 27.3,25.4 C210.2 | v21.27,30.48 22.52,30.48 IC205.3
  Bottom 0.406: v21.27,30.48 21.27,26.67 22.54,25.4 27.3,25.4 v27.94,26.04
N$10
  Top 0.61: R202.2 60.69,82.51 T201.G
N$11
  Bottom 0.61: R203.2 60.69,63.54 T202.G
N$12
  Bottom 0.61: R204.2 60.69,90.21 T203.G
N$13
  Top 0.61: T204.G 60.37,55.88 65.41,55.88 66.04,55.24 66.04,54.34 R205.2
N$14
  Top 0.61: R222.1 LED204.A
N$15
  Top 0.61: R223.1 LED205.A
N$16
  Top 0.406: R224.1 32.66,16.88 JP1.2
N$34
  Top 0.406: IC102.1 37.15,37.78 37.47,38.1 37.47,39.04 C106.2 37.47,39.7 L103.2
RESET  (via drill 0.61 pad 0.81)
  Top 0.406: v27.3,38.1 27.3,43.18 26.91,43.58 IC201.29 20.55,43.58 v19.05,45.09 | S1.1 S1.2 26.92,55.24 v19.05,55.24
  Top 0.61: v59.69,12.7 59.69,11.43 | 59.69,11.43 C201.2 | 59.69,11.43 R201.1
  Bottom 0.406: v27.3,38.1 28.57,38.1 49.2,17.48 54.91,17.48 v59.69,12.7 J202.5 | v19.05,45.09 v19.05,55.24
RXD  (via drill 0.61 pad 0.81)
  Top 0.406: IC201.30 27.38,44.38 28.57,43.18 v28.57,36.2 | IC202.4 v36.2,20.32
  Bottom 0.406: v28.57,36.2 36.2,28.57 v36.2,20.32
S  (via drill 0.61 pad 0.81)
  other vias: 61.91,57.78 58.74,57.78 58.74,59.69 58.74,61.59 61.91,61.59 61.91,59.69 60.33,59.69 60.33,57.78 60.33,61.59 61.91,88.27 61.91,86.36 61.91,84.45 58.74,84.45 58.74,86.36 58.74,88.27 60.33,88.27 60.33,86.36 60.33,84.45
  pour Top (isolate 0.457, rank 3, no thermals): 57.78,99.38 57.78,56.83 66.99,56.83 66.99,72.07 67.63,72.71 78.74,72.71 79.38,73.34 79.38,99.38
  pour Bottom (isolate 0.457, rank 3, no thermals): 57.78,99.38 57.78,55.56 66.99,55.56 66.99,72.07 67.63,72.71 78.74,72.71 79.38,73.34 79.38,99.38
SCK
  Top 0.406: J202.7 57.15,8.26 56.52,8.89 50.16,8.89 47.62,11.43 47.62,17.78 42.55,22.86 11.43,22.86 8.26,26.04 8.26,37.47 9.68,38.89 IC201.17
SPANNUNG  (via drill 0.61 pad 0.81)
  Top 0.406: IC201.24 24.93,38.89 25.4,38.42 v25.4,38.1 C211.2 | IC205.1 24.45,32.65 R216.2 v25.4,32.7
  Bottom 0.406: v25.4,32.7 v25.4,38.1
STROM  (via drill 0.61 pad 0.81)
  Top 0.406: C207.2 22.95,36.88 IC201.23 22.95,40.55 v22.86,40.64
  Bottom 0.406: IC204.3 40.64,27.94 29.21,39.37 24.13,39.37 v22.86,40.64
SW_OUT
  Top 0.61: 32.18,91.01 arc-90 L101.1 32.85,90.81 D102.C
  Top 1.016: IC103.2 32.18,91.01
  pour Top (isolate 0.813, no thermals): 26.35,88.9 26.35,91.44 27.3,92.39 27.62,96.84 28.57,98.11 34.29,98.11 34.29,88.9 33.66,88.27 26.99,88.27
SWITCH  (via drill 0.61 pad 0.81)
  Top 0.406: v62.87,52.7 IC203.4 | IC201.2 22.95,50.07 v22.86,50.16
  Bottom 0.406: v62.87,52.7 60.96,52.7 60.33,52.07 60.33,45.09 59.69,44.45 27.62,44.45 25.4,46.67 25.4,49.53 24.77,50.16 v22.86,50.16
TXD  (via drill 0.61 pad 0.81)
  Top 0.406: IC201.31 27.84,45.18 29.84,43.18 29.84,35.56 v28.57,34.29 | IC202.1 40.01,19.68 v40.64,20.32
  Bottom 0.406: v28.57,34.29 34.92,27.94 34.92,19.68 35.56,19.05 40.01,19.05 40.64,19.68 v40.64,20.32
VS  (via drill 0.61 pad 0.81)
  Top 0.406: 46.99,28.57 44.45,26.04 33.66,26.04 32.07,27.62 R217.1
  Top 0.61: 37.61,97.47 D101.A
  Top 1.016: 60.33,28.57 46.99,28.57 40.64,34.92 40.64,96.84 40.01,97.47 37.61,97.47
  other vias: 61.28,28.57 63.18,28.57 64.14,27.3 64.14,25.4 64.14,23.5 64.14,21.59 60.33,27.3 60.33,25.4 60.33,23.5 60.33,21.59 61.28,20.32 63.18,20.32
  pour Top (isolate 1.016, no thermals): 77.15,19.68 76.52,19.05 60.33,19.05 59.69,19.68 59.69,28.57 60.33,29.21 76.52,29.21 77.15,28.57
  pour Bottom (isolate 1.016, rank 2, no thermals): 77.15,19.68 76.52,19.05 60.33,19.05 59.69,19.68 59.69,28.57 60.33,29.21 76.52,29.21 77.15,28.57
VS_  (via drill 0.61 pad 0.81)
  Top 0.61: IC203.8 59.63,44.55 C206.+ 59.53,39.53 59.55,39.53 IC204.IP-1
  other vias: 61.28,31.11 43.81,39.37 45.72,39.37 47.62,39.37 49.53,39.37 51.44,39.37 53.34,39.37 55.24,39.37 43.81,37.47 45.72,37.47 47.62,37.47 49.53,37.47 51.44,37.47 53.34,37.47 55.24,37.47 63.18,31.11 60.33,32.38 60.33,34.29 60.33,36.2 60.33,38.1 61.28,39.37 64.14,38.1 64.14,36.2 64.14,34.29 64.14,32.38 63.18,39.37
  pour Top (isolate 0.813, rank 2, no thermals): 42.55,41.91 42.55,35.56 47.62,30.48 65.41,30.48 66.04,31.11 66.04,41.27 65.41,41.91
  pour Bottom (isolate 0.813, rank 3, no thermals): 42.55,41.9 42.55,35.56 47.62,30.48 65.41,30.48 66.04,31.11 66.04,41.27 65.41,41.91 55.93,41.92

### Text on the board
Top: IN
Bottom: Uni-Ulm | 09/2010 | Dominic Rathje | PowerMonitor
tStop: OUT | GND | N | I | 5V | GND | 12V
Measures: (0,100) | alle Maße in mm | (80,100) | (80,0) | (0,0)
